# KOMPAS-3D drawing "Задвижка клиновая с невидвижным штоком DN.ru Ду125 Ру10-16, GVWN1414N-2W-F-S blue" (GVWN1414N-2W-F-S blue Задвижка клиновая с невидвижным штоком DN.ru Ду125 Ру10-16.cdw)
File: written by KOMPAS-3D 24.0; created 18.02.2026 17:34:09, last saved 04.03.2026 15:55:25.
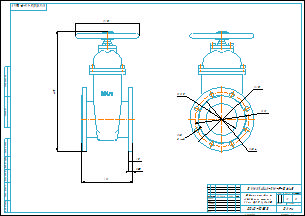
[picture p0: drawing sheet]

Document properties: Автор: R2D2; Форматы листов документа: A2; Полное имя файла: GVWN1414N-2W-F-S blue Задвижка клиновая с невидвижным штоком DN.ru Ду125 Ру10-16.m3d; Масса: 20; Наименование: Задвижка клиновая с невидвижным штоком DN.ru Ду125 Ру10-16; Количество листов документа: 1; Примечание: D040-10583

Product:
- Part/product: Задвижка клиновая с невидвижным штоком DN.ru Ду125 Ру10-16  | designation GVWN1414N-2W-F-S blue
    Масса: 20
    Раздел спецификации: Прочие изделия
    Примечание: D040-10583

Views: Вид 1, Спереди, Проекционный вид 2
Referenced files in E:\Работа\Зайцев\GVWN1414N-2W-F-S blue Задвижка клиновая с невидвижным штоком DN.ru Ду40-300 Ру10-16\DN125\: GVWN1414N-2W-F-S blue Задвижка клиновая с невидвижным штоком DN.ru Ду125 Ру10-16.m3d
Referenced files in E:\Работа\Зайцев\Для компаса\: чертеж DN.ru А3.cdt
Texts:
  GVWN1414N-2W-F-S blue
  чертеж DN.ru А3.cdt
  Задвижка клиновая с
  невидвижным штоком
  DN.ru Ду125 Ру10-16
  Задвижка клиновая с невидвижным штоком DN.ru Ду125 Ру10-16
  GVWN1414N-2W-F-S blue Задвижка клиновая с невидвижным штоком DN.ru Ду125 Ру10-16
Dimensions and other numbers on the sheet: 0; 3; 2; 4; 200; 16,5; 2,5; 470; 250; 210; 184; 125; 18; 8 отв.; 1:2; 1; 20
